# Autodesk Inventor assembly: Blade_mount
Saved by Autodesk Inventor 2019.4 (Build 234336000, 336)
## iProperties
Created: 2020-04
Part Number: Blade_mount
Document SubType Name: Assembly
Designer: Administrator
Title: Blade_mount v18
Author: Administrator
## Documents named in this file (10)
- c:\worker\convert-fusion-r03\tmp\job-1\48\output\files\ccae6ef3-9f0e-42ff-b199-3a2c6474057a\Blade_mount v18.iam
- c:\worker\convert-fusion-r03\tmp\job-1\48\output\files\ccae6ef3-9f0e-42ff-b199-3a2c6474057a\Component1.ipt
- c:\worker\convert-fusion-r03\tmp\job-1\48\output\files\ccae6ef3-9f0e-42ff-b199-3a2c6474057a\Component2.ipt
- c:\worker\convert-fusion-r03\tmp\job-1\48\output\files\ccae6ef3-9f0e-42ff-b199-3a2c6474057a\Component3.ipt
- c:\worker\convert-fusion-r03\tmp\job-1\48\output\files\ccae6ef3-9f0e-42ff-b199-3a2c6474057a\Component4.ipt
- c:\worker\convert-fusion-r03\tmp\job-1\48\output\files\ccae6ef3-9f0e-42ff-b199-3a2c6474057a\Component5.ipt
- c:\worker\convert-fusion-r03\tmp\job-1\48\output\files\ccae6ef3-9f0e-42ff-b199-3a2c6474057a\Component6.ipt
- c:\worker\convert-fusion-r03\tmp\job-1\48\output\files\ccae6ef3-9f0e-42ff-b199-3a2c6474057a\Component7.ipt
- c:\worker\convert-fusion-r03\tmp\job-1\48\output\files\ccae6ef3-9f0e-42ff-b199-3a2c6474057a\Component8.ipt
- c:\worker\convert-fusion-r03\tmp\job-1\48\output\files\ccae6ef3-9f0e-42ff-b199-3a2c6474057a\Component9.ipt
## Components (9 placed, 9 different names)
1. Component1:1
2. Component2:1
3. Component3:1
4. Component4:1
5. Component5:1
6. Component6:1
7. Component7:1
8. Component8:1
9. Component9:1
